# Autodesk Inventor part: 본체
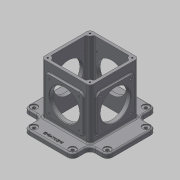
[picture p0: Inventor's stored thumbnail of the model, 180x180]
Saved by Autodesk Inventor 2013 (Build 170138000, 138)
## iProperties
Created: 2018-09
Part Number: 본체
Material: 알루미늄 6061
Document SubType Name: Modeling
Designer: mduedu
Density: 2.71 g/cm^3
Author: mduedu
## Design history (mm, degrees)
sketch "스케치1"
  geometry: L1 (90, 52.5)-(-90, 52.5); L2 (-90, 52.5)-(-90, -52.5); L3 (-90, -52.5)-(90, -52.5); L4 (90, -52.5)-(90, 52.5); L5 (90, 52.5)-(-90, -52.5); L6 (-90, 52.5)-(90, -52.5); L7 (-52.5, -90)-(52.5, -90); L8 (52.5, -90)-(52.5, 90); L9 (52.5, 90)-(-52.5, 90); L10 (-52.5, 90)-(-52.5, -90); L11 (-52.5, -90)-(52.5, 90); L12 (52.5, -90)-(-52.5, 90); 1 further point
  constraints: 24 end point, 4 midpoint, 4 parallel, 2 horizontal, 2 perpendicular
  dimensions: "d0" = 180 distance of L3.end L2.end; "d1" = 105 distance of L2.end L1.end; "d105" = 105 distance of L9.end L8.end; "d106" = 180 distance of L8.end L7.end
extrude "돌출1" new body sketch "스케치1" distance "d2" = 10; taper "d3" = 0 deg
fillet "모깎기16" dims "d107" = 11
sketch "스케치2"
  geometry: L1 (-52.5, -52.5)-(52.5, -52.5); L2 (52.5, -52.5)-(52.5, 52.5); L3 (52.5, 52.5)-(-52.5, 52.5); L4 (-52.5, 52.5)-(-52.5, -52.5); L5 (-52.5, -52.5)-(52.5, 52.5); L6 (52.5, -52.5)-(-52.5, 52.5); 1 further point
  constraints: 12 end point, 2 midpoint, 2 parallel, 1 horizontal, 1 perpendicular
  dimensions: "d4" = 105 distance of L3.end L2.end; "d5" = 105 distance of L2.end L1.end
extrude "돌출2" join sketch "스케치2" distance "d6" = 110; taper "d7" = 0 deg
sketch "스케치14"
  geometry: L1 (-52.5, 52.5)-(52.5, 52.5) reference; L2 (52.5, 52.5)-(52.5, -52.5) reference; L3 (52.5, -52.5)-(-52.5, -52.5) reference; L4 (-52.5, -52.5)-(-52.5, 52.5) reference; L5 (46.5, 46.5)-(-46.5, 46.5); L6 (-46.5, 46.5)-(-46.5, -46.5); L7 (-46.5, -46.5)-(46.5, -46.5); L8 (46.5, -46.5)-(46.5, 46.5); 1 further point
  constraints: 8 end point, 3 other
  dimensions: "d85" = 6 distance between parallel lines of L5 L1
extrude "돌출10" cut sketch "스케치14" stored distance "d86" = 10; taper "d87" = 0 deg
fillet "모깎기1" dims "d12" = 7
sketch "스케치15"
  geometry: A1 r 7 centre (-45.5, 45.5) between (-45.5, 52.5) and (-52.5, 45.5) reference; A2 r 7 centre (45.5, 45.5) between (52.5, 45.5) and (45.5, 52.5) reference; A3 r 7 centre (45.5, -45.5) between (45.5, -52.5) and (52.5, -45.5) reference; A4 r 7 centre (-45.5, -45.5) between (-52.5, -45.5) and (-45.5, -52.5) reference; 5 further points
  constraints: 4 coincident, 4 vertical alignment, 8 other
extrude "돌출11" join sketch "스케치15" stored distance "d88" = 10; taper "d89" = 0 deg
fillet "모깎기15" dims "d90" = 3
sketch "스케치6"
  geometry: L1 (50, 20)-(130, 20); L2 (130, 20)-(130, 100); L3 (130, 100)-(50, 100); L4 (50, 100)-(50, 20); L5 (50, 20)-(130, 100); L6 (130, 20)-(50, 100); L7 (0, 0)-(180, 0) reference; 4 further points
  constraints: 12 end point, 4 midpoint, 2 parallel, 1 horizontal, 1 perpendicular, 1 vertical alignment
  dimensions: "d25" = 80 distance of L3.end L2.end; "d26" = 80 distance of L2.end L1.end; "d27" = 60 distance of point (90, 0) point (90, 60)
extrude "돌출6" join sketch "스케치6" distance "d28" = 3; taper "d29" = 0 deg
fillet "모깎기7" dims "d30" = 8
sketch "스케치7"
  geometry: C1 r 32.5 at (90, 60); 1 further point
  constraints: 1 centre point, 1 vertical alignment
  dimensions: "d32" = 65 diameter of C1; "d33" = 60 distance of C1.centre point (90, 0)
extrude "돌출7" cut sketch "스케치7" stored distance "d34" = 3; taper "d35" = 0 deg
fillet "모깎기9" dims "d36" = 3
sketch "스케치8"
  geometry: L1 (5.5, 10)-(85.5, 10); L2 (85.5, 10)-(85.5, 90); L3 (85.5, 90)-(5.5, 90); L4 (5.5, 90)-(5.5, 10); L5 (5.5, 10)-(85.5, 90); L6 (85.5, 10)-(5.5, 90); L7 (-7, -10)-(98, -10) reference; C1 r 32.5 at (45.5, 50); 4 further points
  constraints: 12 end point, 4 midpoint, 2 parallel, 1 centre point, 1 coincident, 1 horizontal, 1 perpendicular, 1 vertical alignment
  dimensions: "d37" = 80 distance of L3.end L2.end; "d38" = 80 distance of L2.end L1.end; "d39" = 60 distance from line of point (45.5, 50) L7; "d40" = 65 diameter of C1
extrude "돌출8" join sketch "스케치8" distance "d41" = 3; taper "d42" = 0 deg
fillet "모깎기10" dims "d43" = 8
extrude "돌출9" cut sketch "스케치8" stored distance "d44" = 3; taper "d45" = 0 deg
fillet "모깎기11" dims "d46" = 3
sketch "스케치9"
  geometry: L1 (50, 92)-(50, 28) reference; L2 (58, 20)-(122, 20) reference; L3 (130, 28)-(130, 92) reference; L4 (122, 100)-(58, 100) reference; C1 r 32.5 at (90, 60) reference; A1 r 8 centre (58, 92) between (58, 100) and (50, 92) reference; A2 r 8 centre (58, 28) between (50, 28) and (58, 20) reference; A3 r 8 centre (122, 28) between (122, 20) and (130, 28) reference; A4 r 8 centre (122, 92) between (130, 92) and (122, 100) reference; 5 further points
  constraints: 4 coincident
hole "구멍1" sketch "스케치9" at (58, 92), (122, 92), (122, 28), (58, 28) diameter "d47" = 3.242; stored, may be unused: countersink angle "d51" = 90 deg, drill point angle "d53" = 118 deg; dims "d48" = 6, "d49" = 4, "d50" = 2, "d52" = 9
sketch "스케치10"
  geometry: L1 (13.5, 10)-(77.5, 10) reference; L2 (85.5, 18)-(85.5, 82) reference; L3 (77.5, 90)-(13.5, 90) reference; L4 (5.5, 82)-(5.5, 18) reference; C1 r 32.5 at (45.5, 50) reference; A1 r 8 centre (13.5, 18) between (5.5, 18) and (13.5, 10) reference; A2 r 8 centre (77.5, 18) between (77.5, 10) and (85.5, 18) reference; A3 r 8 centre (77.5, 82) between (85.5, 82) and (77.5, 90) reference; A4 r 8 centre (13.5, 82) between (13.5, 90) and (5.5, 82) reference; 5 further points
  constraints: 4 coincident
hole "구멍2" sketch "스케치10" at (13.5, 82), (77.5, 82), (77.5, 18), (13.5, 18) diameter "d54" = 3.242; stored, may be unused: countersink angle "d58" = 90 deg, drill point angle "d60" = 118 deg; dims "d55" = 6, "d56" = 4, "d57" = 2, "d59" = 9
fillet "모깎기12" dims "d68" = 11
sketch "스케치16"
  geometry: A1 r 11 centre (-79, 41.5) between (-79, 52.5) and (-90, 41.5) reference; A2 r 11 centre (-79, -41.5) between (-90, -41.5) and (-79, -52.5) reference; A3 r 11 centre (79, 41.5) between (90, 41.5) and (79, 52.5) reference; A4 r 11 centre (79, -41.5) between (79, -52.5) and (90, -41.5) reference; A5 r 11 centre (-41.5, 79) between (-41.5, 90) and (-52.5, 79) reference; A6 r 11 centre (41.5, 79) between (52.5, 79) and (41.5, 90) reference; A7 r 11 centre (41.5, -79) between (41.5, -90) and (52.5, -79) reference; A8 r 11 centre (-41.5, -79) between (-52.5, -79) and (-41.5, -90) reference; 9 further points
  constraints: 8 coincident
hole "구멍5" sketch "스케치16" at (-79, 41.5), (79, 41.5), (79, -41.5), (-79, -41.5), (41.5, 79), (-41.5, 79), (-41.5, -79), (41.5, -79) diameter "d91" = 6.6; stored, may be unused: countersink angle "d95" = 90 deg, drill point angle "d97" = 118 deg; dims "d92" = 6, "d93" = 15, "d94" = 2, "d96" = 8
fillet "모깎기13" dims "d77" = 3
chamfer "모따기1" distance "d79" = 1; stored, may be unused: second distance "d80" = 2, angle "d81" = 45 deg
sketch "스케치17"
  geometry: A1 r 7 centre (-45.5, 45.5) between (-45.5, 52.5) and (-52.5, 45.5) reference; A2 r 7 centre (-45.5, -45.5) between (-52.5, -45.5) and (-45.5, -52.5) reference; A3 r 7 centre (45.5, -45.5) between (45.5, -52.5) and (52.5, -45.5) reference; A4 r 7 centre (45.5, 45.5) between (52.5, 45.5) and (45.5, 52.5) reference; 5 further points
  constraints: 4 coincident
hole "구멍6" sketch "스케치17" at (-45.5, 45.5), (45.5, 45.5), (45.5, -45.5), (-45.5, -45.5) diameter "d98" = 3.242; stored, may be unused: countersink angle "d102" = 90 deg, drill point angle "d104" = 118 deg; dims "d99" = 8, "d100" = 15, "d101" = 2, "d103" = 10
sketch "스케치13"
  geometry: L1 (90, -41.5)-(90, 41.5) reference; 2 further points
  constraints: 1 horizontal alignment, 1 other
  dimensions: "d82" = 11 distance from line of point (79, 0) L1
feature "엠보싱1" sketch "스케치13" dims "d0" = 180, "d1" = 105, "d83" = 0.5, "d84" = 0
node "솔리드1"
mirror "대칭1"
mirror "대칭4"
mirror "대칭2"
mirror "대칭5"
node "투영된 루프2"
node "투영된 루프3"
node "투영된 루프6"
